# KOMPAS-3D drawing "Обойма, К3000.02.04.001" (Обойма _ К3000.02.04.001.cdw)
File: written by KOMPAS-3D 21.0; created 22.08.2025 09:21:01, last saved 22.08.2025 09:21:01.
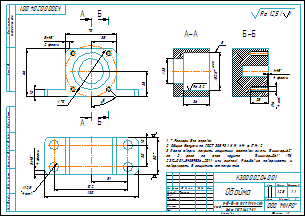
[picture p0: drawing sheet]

Sheet 1: A3, landscape

Document properties: Автор: Lutik; Полное имя файла: C:\Users\Lutik\YandexDisk\Документы\Новая папка\Бабка задняя\2D\Подшипниковый узел_К3000.02.04.000\Обойма _ К3000.02.04.001.cdw; Знак неуказанной шероховатости: 4; Параметр неуказанной шероховатости: Ra 12,5; Масса: 1.275202

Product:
- Part/product: Обойма  | designation К3000.02.04.001
    Материал: Лист$dБ-ПН-НО-50 ГОСТ 19903-2015;Ст3сп ГОСТ 14637-89$ (density 7850 kg/m3)
    Масса: 1.275202

Title block, sheet 1: Наименование: Обойма; designation: К3000.02.04.001; Материал: Лист Б-ПН-НО-50 ГОСТ 19903-2015 Ст3сп ГОСТ 14637-89; Масса: 1,28; Количество листов документа: 1; organisation: ООО "МИРО"; Форматы листов документа: A3; Разработал: Тимонин

Views: Вид 1, Слева, Проекционный вид 2, Разрез А-А, Разрез Б-Б
Referenced files in C:\Users\Lutik\YandexDisk\Документы\Новая папка\Бабка задняя\3D\: Обойма_33.m3d
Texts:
  Ra 3,2
  Ra 12,5
  Ra 12,5 ( )
  К3000.02.04.001 Обойма
Dimensions and other numbers on the sheet: 10; 66; 70; 5; 2 фаски; 35; 4 фаски; 30; 51; 102; 12,5; 4 отв.; 130; 50; 52; 36; 25; 6; 1; 1:1; 1,28

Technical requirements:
  * Размеры для справок.
  Общие допуски по ГОСТ 30893.1: Н14, h14, ± IT14/2.
  После сварки покрыть защитным составом эмаль "Виникор-62"
  за 2 раза по слою грунта  "Виникор-061" (ТУ
  2312-001-54359536-2011 или аналог). Резьбовые поверхности и
  поверхность В защитить от покрытия.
